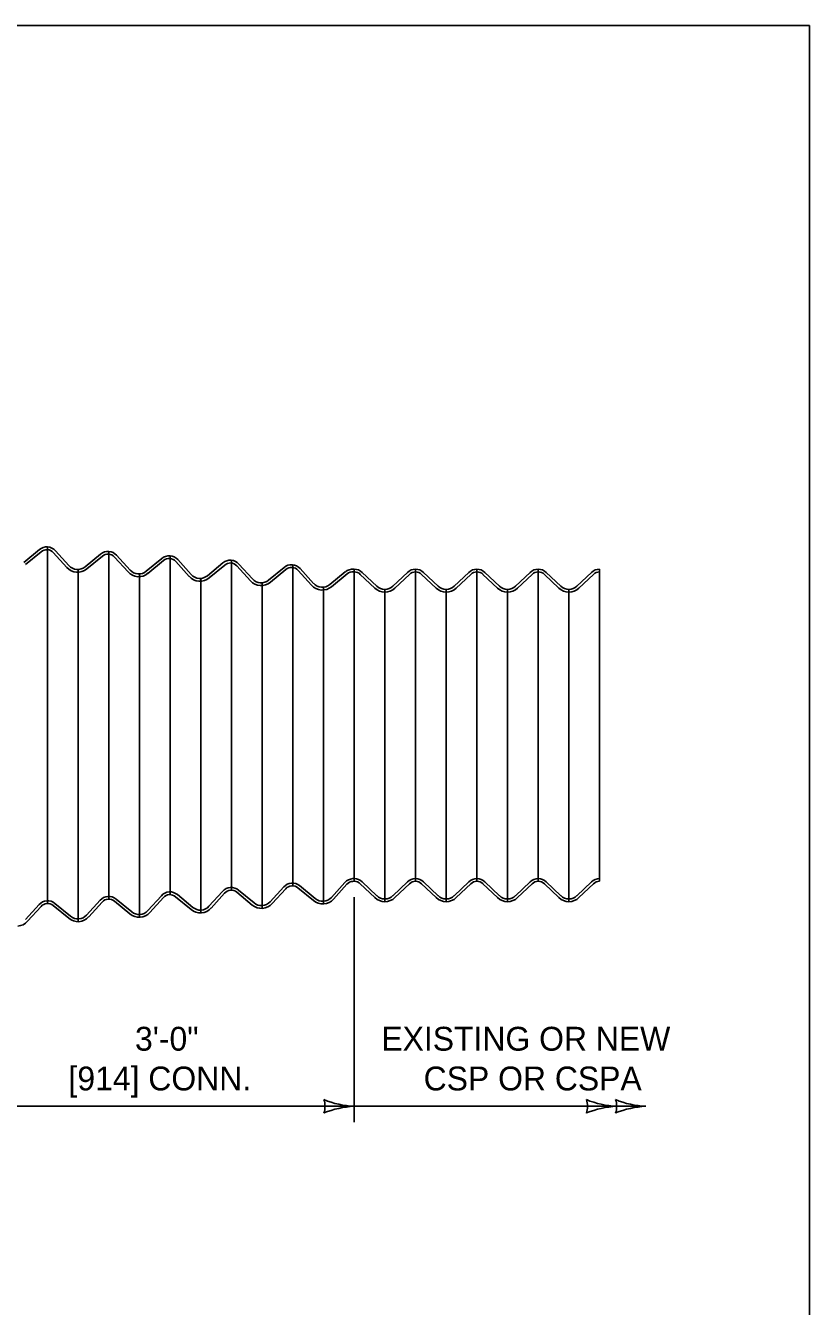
# Model space of a CAD drawing. Extents: x 49991.4 to 50021, y 49987.6 to 50011.4.
# Drawn here: x 50006.644 to 50008.615, y 50008.041 to 50011.263 of the extents above; entities that cross this region are included whole.
import ezdxf

# ---------------------------------------------------------------- set-up
doc = ezdxf.new("R2010")
doc.units = 0
for name, color, linetype in [('Level 1', 7, 'Continuous'), ('Level 2', 7, 'Continuous'), ('Level 3', 7, 'Continuous')]:
    doc.layers.add(name, color=color, linetype=linetype)

msp = doc.modelspace()

# ---------------------------------------------------------------- linework, layer by layer
at = {"layer": 'Level 1'}
for p, q in [((50006.6392, 50009.9126), (50006.6783, 50009.9448)), ((50006.6437, 50009.9074), (50006.6827, 50009.9395)), ((50006.6986, 50009.9515), (50006.6986, 50009.0545)), ((50006.7474, 50009.8998), (50006.7132, 50009.9374)), ((50006.7526, 50009.9044), (50006.7185, 50009.9419)), ((50006.8321, 50009.9336), (50006.7931, 50009.9014)), ((50006.8366, 50009.9283), (50006.7976, 50009.8962)), ((50006.8529, 50009.9403), (50006.8529, 50009.0657)), ((50006.8673, 50009.9261), (50006.9012, 50009.8886)), ((50006.8724, 50009.9306), (50006.9064, 50009.8932)), ((50006.947, 50009.8903), (50006.986, 50009.9224)), ((50007.0071, 50009.9291), (50007.0071, 50009.0768)), ((50006.7758, 50009.8946), (50006.7758, 50009.0086)), ((50006.9514, 50009.885), (50006.9905, 50009.9171)), ((50007.0551, 50009.8774), (50007.0211, 50009.9149)), ((50007.0603, 50009.882), (50007.0263, 50009.9195)), ((50007.1399, 50009.9112), (50007.1008, 50009.8791)), ((50007.1444, 50009.9059), (50007.1053, 50009.8738)), ((50007.1614, 50009.9179), (50007.1614, 50009.0879)), ((50007.2089, 50009.8663), (50007.175, 50009.9037)), ((50007.2141, 50009.8708), (50007.1801, 50009.9083)), ((50007.2937, 50009.9), (50007.2547, 50009.8679)), ((50007.2982, 50009.8947), (50007.2591, 50009.8626)), ((50007.3157, 50009.9066), (50007.3157, 50009.099)), ((50007.3288, 50009.8925), (50007.3628, 50009.8551)), ((50007.334, 50009.8971), (50007.368, 50009.8596)), ((50007.4085, 50009.8567), (50007.4476, 50009.8888)), ((50007.4678, 50009.8886), (50007.47, 50009.8887)), ((50007.4683, 50009.8955), (50007.47, 50009.8957)), ((50007.4699, 50009.8957), (50007.4699, 50009.1104)), ((50007.6242, 50009.8957), (50007.6242, 50009.1104)), ((50007.7785, 50009.8957), (50007.7785, 50009.1104)), ((50007.9327, 50009.8957), (50007.9327, 50009.1104)), ((50008.087, 50009.8957), (50008.087, 50009.1104)), ((50006.93, 50009.8834), (50006.93, 50009.0198)), ((50007.0843, 50009.8722), (50007.0843, 50009.0309)), ((50007.2386, 50009.8611), (50007.2386, 50009.0421)), ((50007.413, 50009.8514), (50007.4521, 50009.8835)), ((50007.5219, 50009.8476), (50007.4853, 50009.8825)), ((50007.5268, 50009.8526), (50007.4902, 50009.8874)), ((50007.604, 50009.8874), (50007.5674, 50009.8526)), ((50007.6089, 50009.8825), (50007.5723, 50009.8476)), ((50007.6762, 50009.8476), (50007.6396, 50009.8825)), ((50007.681, 50009.8526), (50007.6444, 50009.8874)), ((50007.7583, 50009.8874), (50007.7216, 50009.8526)), ((50007.7631, 50009.8825), (50007.7265, 50009.8476)), ((50007.7938, 50009.8825), (50007.8304, 50009.8476)), ((50007.7987, 50009.8874), (50007.8353, 50009.8526)), ((50007.8759, 50009.8526), (50007.9126, 50009.8874)), ((50007.8808, 50009.8476), (50007.9174, 50009.8825)), ((50007.9847, 50009.8476), (50007.9481, 50009.8825)), ((50007.9896, 50009.8526), (50007.953, 50009.8874)), ((50008.0668, 50009.8874), (50008.0302, 50009.8526)), ((50008.0717, 50009.8825), (50008.0351, 50009.8476)), ((50007.3928, 50009.8499), (50007.3928, 50009.0532)), ((50007.5471, 50009.8442), (50007.5471, 50009.059)), ((50007.7014, 50009.8442), (50007.7014, 50009.059)), ((50007.8556, 50009.8442), (50007.8556, 50009.059)), ((50008.0099, 50009.8442), (50008.0099, 50009.059)), ((50007.4661, 50009.117), (50007.47, 50009.1173)), ((50007.1389, 50009.0851), (50007.1048, 50009.0477)), ((50007.2182, 50009.0559), (50007.1791, 50009.088)), ((50007.2927, 50009.0962), (50007.2587, 50009.0588)), ((50007.2979, 50009.0917), (50007.2639, 50009.0542)), ((50007.3285, 50009.0939), (50007.3676, 50009.0617)), ((50007.3327, 50009.0994), (50007.372, 50009.067)), ((50007.4126, 50009.0699), (50007.4466, 50009.1074)), ((50007.4178, 50009.0654), (50007.4518, 50009.1028)), ((50007.4666, 50009.1101), (50007.47, 50009.1104)), ((50007.5219, 50009.0693), (50007.4853, 50009.1041)), ((50007.5268, 50009.0742), (50007.4902, 50009.1091)), ((50007.604, 50009.1091), (50007.5674, 50009.0742)), ((50007.6089, 50009.1041), (50007.5723, 50009.0693)), ((50007.6762, 50009.0693), (50007.6396, 50009.1041)), ((50007.681, 50009.0742), (50007.6444, 50009.1091)), ((50007.7583, 50009.1091), (50007.7216, 50009.0742)), ((50007.7631, 50009.1041), (50007.7265, 50009.0693)), ((50007.7938, 50009.1041), (50007.8304, 50009.0693)), ((50007.7987, 50009.1091), (50007.8353, 50009.0742)), ((50007.8759, 50009.0742), (50007.9126, 50009.1091)), ((50007.8808, 50009.0693), (50007.9174, 50009.1041)), ((50007.9847, 50009.0693), (50007.9481, 50009.1041)), ((50007.9896, 50009.0742), (50007.953, 50009.1091)), ((50008.0668, 50009.1091), (50008.0302, 50009.0742)), ((50008.0717, 50009.1041), (50008.0351, 50009.0693)), ((50006.6432, 50009.0143), (50006.6775, 50009.0519)), ((50006.7566, 50009.0225), (50006.7175, 50009.0546)), ((50006.8311, 50009.0628), (50006.7971, 50009.0254)), ((50006.8363, 50009.0582), (50006.8023, 50009.0208)), ((50006.8669, 50009.0605), (50006.906, 50009.0283)), ((50006.8714, 50009.0658), (50006.9105, 50009.0336)), ((50006.951, 50009.0365), (50006.985, 50009.074)), ((50006.9562, 50009.032), (50006.9902, 50009.0694)), ((50007.0598, 50009.0395), (50007.0208, 50009.0716)), ((50007.0643, 50009.0447), (50007.0253, 50009.0769)), ((50007.144, 50009.0805), (50007.11, 50009.0431)), ((50007.2137, 50009.0506), (50007.1746, 50009.0827)), ((50006.6484, 50009.0097), (50006.6824, 50009.0471)), ((50006.6824, 50009.0471), (50006.6824, 50009.0471)), ((50006.7521, 50009.0172), (50006.7131, 50009.0493)), ((50006.6484, 50009.0097), (50006.6484, 50009.0097))]:
    msp.add_line(p, q, dxfattribs=at)
msp.add_lwpolyline([(50008.6146, 50011.2628), (50000.3356, 50011.2628), (50000.3356, 50000.0624), (50008.6146, 50000.0624)], close=True, dxfattribs=at)
for centre, radius, start, end in [((50006.6969, 50009.9226), 0.0289, 85.8403, 130.1334), ((50006.6969, 50009.9226), 0.022, 85.8403, 130.1334), ((50006.8508, 50009.9115), 0.0289, 85.8403, 130.1334), ((50006.8508, 50009.9115), 0.022, 85.8403, 130.1334), ((50006.8508, 50009.9115), 0.022, 41.5472, 85.8403), ((50006.8508, 50009.9115), 0.0289, 41.5472, 85.8403), ((50007.0047, 50009.9003), 0.0289, 85.8403, 130.1334), ((50007.0047, 50009.9003), 0.022, 85.8403, 130.1334), ((50007.0047, 50009.9003), 0.022, 41.5472, 85.8403), ((50007.0047, 50009.9003), 0.0289, 41.5472, 85.8403), ((50006.7743, 50009.9235), 0.0358, 221.2467, 265.8403), ((50006.7743, 50009.9235), 0.0289, 221.2467, 265.8403), ((50006.7743, 50009.9235), 0.0358, 265.8403, 310.4339), ((50006.7743, 50009.9235), 0.0289, 265.8403, 310.4339), ((50006.9282, 50009.9123), 0.0358, 221.2467, 265.8403), ((50006.9282, 50009.9123), 0.0289, 221.2467, 265.8403), ((50006.9282, 50009.9123), 0.0289, 265.8403, 310.4339), ((50007.1585, 50009.8891), 0.0289, 85.8403, 130.1334), ((50007.1585, 50009.8891), 0.022, 85.8403, 130.1334), ((50007.1585, 50009.8891), 0.022, 41.5472, 85.8403), ((50007.1585, 50009.8891), 0.0289, 41.5472, 85.8403), ((50007.3124, 50009.8779), 0.0289, 85.8403, 130.1334), ((50007.3124, 50009.8779), 0.022, 85.8403, 130.1334), ((50007.3124, 50009.8779), 0.022, 41.5472, 85.8403), ((50007.3124, 50009.8779), 0.0289, 41.5472, 85.8403), ((50007.4663, 50009.8667), 0.0289, 85.8403, 130.1334), ((50007.4663, 50009.8667), 0.022, 85.8403, 130.1334), ((50007.47, 50009.8667), 0.0289, 45.7069, 90), ((50007.47, 50009.8667), 0.022, 45.7069, 90), ((50007.6242, 50009.8667), 0.0289, 90, 134.2931), ((50007.6242, 50009.8667), 0.022, 90, 134.2931), ((50007.6242, 50009.8667), 0.0289, 45.7069, 90), ((50007.6242, 50009.8667), 0.022, 45.7069, 90), ((50007.7785, 50009.8667), 0.0289, 90, 134.2931), ((50007.7785, 50009.8667), 0.022, 90, 134.2931), ((50007.7785, 50009.8667), 0.0289, 45.7069, 90), ((50007.7785, 50009.8667), 0.022, 45.7069, 90), ((50007.9328, 50009.8667), 0.0289, 90, 134.2931), ((50007.9328, 50009.8667), 0.022, 90, 134.2931), ((50007.9328, 50009.8667), 0.0289, 45.7069, 90), ((50007.9328, 50009.8667), 0.022, 45.7069, 90), ((50008.087, 50009.8667), 0.0289, 90.0798, 134.2931), ((50008.087, 50009.8667), 0.022, 90.1049, 134.2931), ((50006.9282, 50009.9123), 0.0358, 265.8403, 310.4339), ((50007.0821, 50009.9011), 0.0358, 221.2467, 265.8403), ((50007.0821, 50009.9011), 0.0289, 221.2467, 265.8403), ((50007.0821, 50009.9011), 0.0358, 265.8403, 310.4339), ((50007.0821, 50009.9011), 0.0289, 265.8403, 310.4339), ((50007.2359, 50009.8899), 0.0358, 221.2467, 265.8403), ((50007.2359, 50009.8899), 0.0289, 221.2467, 265.8403), ((50007.2359, 50009.8899), 0.0358, 265.8403, 310.4339), ((50007.2359, 50009.8899), 0.0289, 265.8403, 310.4339), ((50007.3898, 50009.8787), 0.0289, 221.2467, 265.8403), ((50007.3898, 50009.8787), 0.0289, 265.8403, 310.4339), ((50007.3898, 50009.8787), 0.0358, 221.2467, 265.8403), ((50007.3898, 50009.8787), 0.0358, 265.8403, 310.4339), ((50007.5471, 50009.8732), 0.0358, 225.4064, 270), ((50007.5471, 50009.8732), 0.0289, 225.4064, 270), ((50007.5471, 50009.8732), 0.0289, 270, 314.5936), ((50007.5471, 50009.8732), 0.0358, 270, 314.5936), ((50007.7013, 50009.8732), 0.0358, 225.4064, 270), ((50007.7013, 50009.8732), 0.0289, 225.4064, 270), ((50007.7013, 50009.8732), 0.0289, 270, 314.5936), ((50007.7013, 50009.8732), 0.0358, 270, 314.5936), ((50007.8556, 50009.8732), 0.0358, 225.4064, 270), ((50007.8556, 50009.8732), 0.0289, 225.4064, 270), ((50007.8556, 50009.8732), 0.0289, 270, 314.5936), ((50007.8556, 50009.8732), 0.0358, 270, 314.5936), ((50008.0099, 50009.8732), 0.0358, 225.4064, 270), ((50008.0099, 50009.8732), 0.0289, 225.4064, 270), ((50008.0099, 50009.8732), 0.0289, 270, 314.5936), ((50008.0099, 50009.8732), 0.0358, 270, 314.5936), ((50007.4682, 50009.0882), 0.0289, 94.1392, 138.4323), ((50007.47, 50009.0884), 0.0289, 45.7069, 90), ((50007.6242, 50009.0884), 0.0289, 90, 134.2931), ((50007.6242, 50009.0884), 0.0289, 45.7069, 90), ((50007.7785, 50009.0884), 0.0289, 90, 134.2931), ((50007.7785, 50009.0884), 0.0289, 45.7069, 90), ((50007.9328, 50009.0884), 0.0289, 90, 134.2931), ((50007.9328, 50009.0884), 0.0289, 45.7069, 90), ((50008.087, 50009.0884), 0.0289, 90.0798, 134.2931), ((50007.0066, 50009.0548), 0.0289, 94.1392, 138.4323), ((50007.0066, 50009.0548), 0.0289, 49.8462, 94.1392), ((50007.1605, 50009.0659), 0.0289, 94.1392, 138.4323), ((50007.1605, 50009.0659), 0.022, 94.1392, 138.4323), ((50007.1605, 50009.0659), 0.0289, 49.8462, 94.1392), ((50007.1605, 50009.0659), 0.022, 49.8462, 94.1392), ((50007.3143, 50009.077), 0.0289, 94.1392, 138.4323), ((50007.3143, 50009.077), 0.022, 94.1392, 138.4323), ((50007.3143, 50009.077), 0.0289, 49.8462, 94.1392), ((50007.3143, 50009.077), 0.022, 49.8462, 94.1392), ((50007.4682, 50009.0882), 0.022, 94.1392, 138.4323), ((50007.47, 50009.0884), 0.022, 45.7069, 90), ((50007.6242, 50009.0884), 0.022, 90, 134.2931), ((50007.6242, 50009.0884), 0.022, 45.7069, 90), ((50007.7785, 50009.0884), 0.022, 90, 134.2931), ((50007.7785, 50009.0884), 0.022, 45.7069, 90), ((50007.9328, 50009.0884), 0.022, 90, 134.2931), ((50007.9328, 50009.0884), 0.022, 45.7069, 90), ((50008.087, 50009.0884), 0.022, 90.1049, 134.2931), ((50006.6989, 50009.0325), 0.022, 94.1392, 138.4323), ((50006.6989, 50009.0325), 0.0289, 49.8462, 94.1392), ((50006.6989, 50009.0325), 0.022, 49.8462, 94.1392), ((50006.8527, 50009.0436), 0.0289, 94.1392, 138.4323), ((50006.8527, 50009.0436), 0.022, 94.1392, 138.4323), ((50006.8527, 50009.0436), 0.0289, 49.8462, 94.1392), ((50006.8527, 50009.0436), 0.022, 49.8462, 94.1392), ((50007.0066, 50009.0548), 0.022, 94.1392, 138.4323), ((50007.0066, 50009.0548), 0.022, 49.8462, 94.1392), ((50007.2369, 50009.0779), 0.0289, 229.5456, 274.1392), ((50007.2369, 50009.0779), 0.0289, 274.1392, 318.7329), ((50007.2369, 50009.0779), 0.0358, 274.1392, 318.7329), ((50007.3908, 50009.089), 0.0358, 229.5456, 274.1392), ((50007.3908, 50009.089), 0.0289, 229.5456, 274.1392), ((50007.3908, 50009.089), 0.0289, 274.1392, 318.7329), ((50007.3908, 50009.089), 0.0358, 274.1392, 318.7329), ((50007.5471, 50009.0948), 0.0358, 225.4064, 270), ((50007.5471, 50009.0948), 0.0289, 225.4064, 270), ((50007.5471, 50009.0948), 0.0289, 270, 314.5936), ((50007.5471, 50009.0948), 0.0358, 270, 314.5936), ((50007.7013, 50009.0948), 0.0358, 225.4064, 270), ((50007.7013, 50009.0948), 0.0289, 225.4064, 270), ((50007.7013, 50009.0948), 0.0289, 270, 314.5936), ((50007.7013, 50009.0948), 0.0358, 270, 314.5936), ((50007.8556, 50009.0948), 0.0358, 225.4064, 270), ((50007.8556, 50009.0948), 0.0289, 225.4064, 270), ((50007.8556, 50009.0948), 0.0289, 270, 314.5936), ((50007.8556, 50009.0948), 0.0358, 270, 314.5936), ((50008.0099, 50009.0948), 0.0358, 225.4064, 270), ((50008.0099, 50009.0948), 0.0289, 225.4064, 270), ((50008.0099, 50009.0948), 0.0289, 270, 314.5936), ((50008.0099, 50009.0948), 0.0358, 270, 314.5936), ((50006.7753, 50009.0445), 0.0289, 229.5456, 274.1392), ((50006.7753, 50009.0445), 0.0289, 274.1392, 318.7329), ((50006.7753, 50009.0445), 0.0358, 274.1392, 318.7329), ((50006.9292, 50009.0556), 0.0358, 229.5456, 274.1392), ((50006.9292, 50009.0556), 0.0289, 229.5456, 274.1392), ((50006.9292, 50009.0556), 0.0289, 274.1392, 318.7329), ((50006.9292, 50009.0556), 0.0358, 274.1392, 318.7329), ((50007.0831, 50009.0668), 0.0358, 229.5456, 274.1392), ((50007.0831, 50009.0668), 0.0289, 229.5456, 274.1392), ((50007.0831, 50009.0668), 0.0289, 274.1392, 318.7329), ((50007.0831, 50009.0668), 0.0358, 274.1392, 318.7329), ((50007.2369, 50009.0779), 0.0358, 229.5456, 274.1392), ((50006.6215, 50009.0333), 0.0358, 274.1392, 318.7329), ((50006.7753, 50009.0445), 0.0358, 229.5456, 274.1392)]:
    msp.add_arc(centre, radius, start, end, dxfattribs=at)
for centre, major_axis, ratio, start_param, end_param in [((50006.6969, 50009.923), (0.0217, -0.0016), 0.997243, 0.797736, 1.570796), ((50006.6969, 50009.9229), (0.0287, -0.0021), 0.995464, 0.797736, 1.570796), ((50006.6988, 50009.0332), (-0.0284, -0.0021), 0.991642, 4.712389, 5.485449)]:
    msp.add_ellipse(centre, major_axis=major_axis, ratio=ratio, start_param=start_param, end_param=end_param, dxfattribs=at)
at = {"layer": 'Level 3'}
for p, q in [((50007.4699, 50009.0704), (50007.4699, 50008.5043)), ((50006.5671, 50008.5443), (50007.4699, 50008.5443)), ((50007.4699, 50008.5443), (50008.2033, 50008.5443))]:
    msp.add_line(p, q, dxfattribs=at)
for centre, radius, start, end in [((50007.4791, 50008.7664), 0.2223, 247.456, 267.6395), ((50007.3417, 50008.5443), 0.0548, 342.1388, 17.8612), ((50007.4814, 50008.3116), 0.233, 92.8273, 112.0772), ((50008.139, 50008.7664), 0.2223, 247.456, 267.6395), ((50008.0017, 50008.5443), 0.0548, 342.1388, 17.8612), ((50008.1414, 50008.3116), 0.233, 92.8273, 112.0772), ((50008.2125, 50008.7664), 0.2223, 247.456, 267.6395), ((50008.0751, 50008.5443), 0.0548, 342.1388, 17.8612), ((50008.2148, 50008.3116), 0.233, 92.8273, 112.0772)]:
    msp.add_arc(centre, radius, start, end, dxfattribs=at)

# ---------------------------------------------------------------- texts
at = {"layer": 'Level 2'}
for s, p in [('3\'-0"', (50006.9188, 50008.6843)), ('EXISTING OR NEW', (50007.5382, 50008.6843)), ('[914] CONN.', (50006.7515, 50008.5843)), ('CSP OR CSPA', (50007.6446, 50008.5843))]:
    msp.add_text(s, height=0.06, dxfattribs=at).set_placement(p)

doc.saveas('drawing.dxf')
